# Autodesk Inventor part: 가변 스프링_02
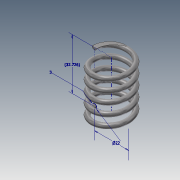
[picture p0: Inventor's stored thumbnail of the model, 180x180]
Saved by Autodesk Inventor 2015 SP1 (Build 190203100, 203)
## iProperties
Created: 2015-05
Part Number: 가변 스프링_02
Material: 강철, 탄소
Document SubType Name: Modeling
Designer: jckim
Density: 7.85 g/cm^3
Appearance: 반연마
Mass: 18.7977 g
Surface Area: 32.507 cm^2
Volume: 2.39461 cm^3
Author: jckim
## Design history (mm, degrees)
sketch "스케치1"
  geometry: L1 (0, 0)-(11, 0); L2 (11, 0)-(11, 32.726); L3 (11, 32.726)-(0, 32.726); L4 (0, 32.726)-(0, 0); C1 r 1.5 at (11, 0)
  constraints: 8 end point, 2 parallel, 1 centre point, 1 coincident, 1 horizontal, 1 perpendicular
  dimensions: "d0" = 3 diameter of C1; "d1" = 22 diameter of L2 L4; "d3" = 32.72647 distance of L1.end L2.end (derived)
feature "코일1" pitch "d4" = 10; turns "d6" = 5; dims "d5" = 32.72647 (= d3), "d7" = 0, angle "d8" = 90 deg, angle "d9" = 90 deg, "d10" = 0, "d11" = 0
sketch "스케치2"
  geometry: L1 (-12.5, 0)-(-9.5, 0) reference; 1 further point
  constraints: 1 horizontal alignment
extrude "돌출1" cut sketch "스케치2" stored distance "d12" = 10; taper "d13" = 0 deg
node "작업 평면1"
sketch "스케치3"
  geometry: L1 (1.5, 0)-(-1.5, 0) reference; 1 further point
  constraints: 1 horizontal alignment
extrude "돌출2" cut sketch "스케치3" stored distance "d15" = 10; taper "d16" = 0 deg
node "솔리드1"
node "절단 모서리 투영1"
node "절단 모서리 투영2"
other parameters: "d14" = 0
